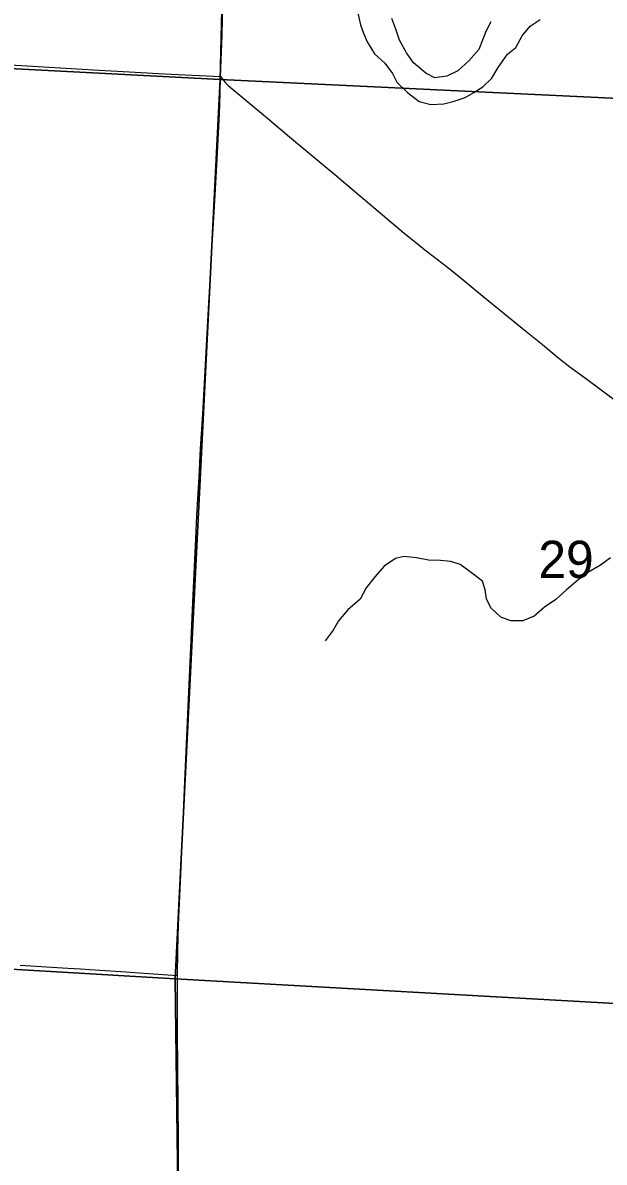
# Model space of a CAD drawing. Extents: x 0 to 34, y 0 to 22.
# Drawn here: x 4.194 to 4.521, y 18.123 to 18.765 of the extents above; entities that cross this region are included whole.
import ezdxf

# ---------------------------------------------------------------- set-up
doc = ezdxf.new("R2010")
doc.units = 0
for name, color, linetype in [('GM_X_Corporation', 7, 'Continuous'), ('GM_X_County_Road', 7, 'Continuous'), ('GM_X_Major_River', 7, 'Continuous'), ('GM_X_Minor_River', 7, 'Continuous'), ('GM_X_Section_Text', 7, 'Continuous'), ('GM_X_State_Route', 7, 'Continuous'), ('GM_X_Township_Road', 7, 'Continuous')]:
    doc.layers.add(name, color=color, linetype=linetype)

msp = doc.modelspace()

# ---------------------------------------------------------------- linework, layer by layer
at = {"layer": 'GM_X_Corporation'}
for points in [[(3.81726, 19.25969), (4.31726, 19.25364), (4.30478, 18.73265), (3.80532, 18.75879)], [(4.31726, 19.25364), (4.81832, 19.23733), (4.81833, 19.23053), (4.81838, 19.17289), (4.81112, 19.17156), (4.80638, 19.17156), (4.80163, 19.172), (4.79778, 19.17363), (4.79126, 19.17541), (4.78267, 19.18), (4.77911, 19.18223), (4.77393, 19.18637), (4.77022, 19.18978), (4.76548, 19.19363), (4.76089, 19.19793), (4.75511, 19.20267), (4.75185, 19.2049), (4.74889, 19.20623), (4.74607, 19.20756), (4.73633, 18.74761), (4.561, 18.7477), (4.54503, 18.72127), (4.30478, 18.73265)], [(4.30478, 18.73265), (4.27934, 18.22655), (3.77934, 18.25611), (3.80532, 18.75879)], [(3.77934, 18.25611), (4.27934, 18.22655), (4.28542, 17.75394), (3.7492, 17.7546)], [(4.27934, 18.22655), (4.66117, 18.20518), (4.66186, 18.19617), (4.66594, 18.18364), (4.67032, 18.16257), (4.67175, 18.15081), (4.67108, 18.13774), (4.67023, 18.12562), (4.66614, 18.11087), (4.66231, 18.10465), (4.65694, 18.09654), (4.65291, 18.09051), (4.65118, 18.08635), (4.64735, 18.08108), (4.73395, 18.08156), (4.72704, 17.74623), (4.28542, 17.75394)]]:
    msp.add_lwpolyline(points, close=True, dxfattribs=at)
msp.add_lwpolyline([(4.66117, 18.20518), (4.27934, 18.22655), (4.30478, 18.73265), (4.54503, 18.72127)], dxfattribs=at)
at = {"layer": 'GM_X_County_Road'}
msp.add_lwpolyline([(4.192, 18.23424), (4.21899, 18.23259), (4.22613, 18.23214), (4.23698, 18.23144), (4.24877, 18.23062), (4.26985, 18.22917), (4.28067, 18.22848)], dxfattribs=at)
at = {"layer": 'GM_X_Major_River'}
for points in [[(4.38239, 18.7699), (4.38387, 18.76344), (4.38554, 18.75868), (4.38759, 18.75374), (4.39172, 18.74707), (4.39756, 18.74191), (4.40187, 18.736), (4.4043, 18.73105), (4.41033, 18.72532), (4.41693, 18.72016), (4.42336, 18.7186), (4.43075, 18.71894), (4.43606, 18.72023), (4.4427, 18.72247), (4.44764, 18.72529), (4.45278, 18.72849), (4.45773, 18.73339), (4.46137, 18.73944), (4.46653, 18.74682), (4.47129, 18.75058), (4.47493, 18.7572), (4.47932, 18.76268), (4.48503, 18.76645)], [(4.45718, 18.76509), (4.45449, 18.7596), (4.45256, 18.75468), (4.45045, 18.74957), (4.44491, 18.74315), (4.43863, 18.73749), (4.43236, 18.73449), (4.42572, 18.73358), (4.42063, 18.73627), (4.41366, 18.742), (4.40971, 18.74772), (4.40578, 18.75477), (4.40374, 18.76104), (4.4015, 18.76694)]]:
    msp.add_lwpolyline(points, dxfattribs=at)
at = {"layer": 'GM_X_Minor_River'}
msp.add_lwpolyline([(4.52457, 18.46348), (4.51905, 18.45934), (4.51183, 18.45521), (4.50631, 18.45088), (4.49983, 18.44541), (4.49393, 18.43994), (4.48746, 18.43562), (4.48156, 18.43072), (4.47529, 18.4281), (4.46847, 18.42795), (4.4628, 18.43007), (4.45715, 18.43541), (4.45472, 18.44036), (4.454, 18.44549), (4.45252, 18.45043), (4.44554, 18.4556), (4.43989, 18.45981), (4.43478, 18.46136), (4.42891, 18.46196), (4.4221, 18.46219), (4.41529, 18.46356), (4.40828, 18.46417), (4.40354, 18.46306), (4.39707, 18.45873), (4.39211, 18.45288), (4.38696, 18.44665), (4.3837, 18.44021), (4.37665, 18.43418), (4.3715, 18.42795), (4.36843, 18.42284), (4.36385, 18.4168)], dxfattribs=at)
at = {"layer": 'GM_X_State_Route'}
msp.add_lwpolyline([(4.28154, 18.09965), (4.28121, 18.13602), (4.28083, 18.17674), (4.28069, 18.19663), (4.28067, 18.22848), (4.28098, 18.24256), (4.28131, 18.2572), (4.28275, 18.28949), (4.28488, 18.33763), (4.28716, 18.38824), (4.28849, 18.41712), (4.28943, 18.43854), (4.29103, 18.47425), (4.29169, 18.48729), (4.29286, 18.50902), (4.29375, 18.52483), (4.2949, 18.54439), (4.29648, 18.57231), (4.29806, 18.60024), (4.30011, 18.63594), (4.30204, 18.67101), (4.30326, 18.69148), (4.30439, 18.7134), (4.30472, 18.7245), (4.30497, 18.7344), (4.30587, 18.75749), (4.30631, 18.77582)], dxfattribs=at)
at = {"layer": 'GM_X_Township_Road'}
for points in [[(3.92462, 18.75398), (3.92513, 18.75396), (3.9372, 18.75351), (3.95081, 18.75299), (3.98465, 18.75147), (4.0039, 18.75057), (4.01879, 18.74992), (4.06367, 18.74774), (4.08273, 18.74681), (4.09793, 18.74593), (4.1274, 18.74415), (4.1485, 18.74302), (4.17642, 18.7414), (4.19597, 18.74029), (4.2332, 18.73812), (4.25678, 18.73675), (4.27322, 18.73577), (4.30497, 18.7344)], [(4.30497, 18.7344), (4.30653, 18.73242), (4.30777, 18.73078), (4.30933, 18.72922), (4.33134, 18.7109), (4.34273, 18.70127), (4.35487, 18.69109), (4.3616, 18.68558), (4.37047, 18.67827), (4.38044, 18.66985), (4.38895, 18.66261), (4.40102, 18.65235), (4.4084, 18.64618), (4.41564, 18.64031), (4.42002, 18.63683), (4.4247, 18.63324), (4.43209, 18.62757), (4.43845, 18.6226), (4.4528, 18.6107), (4.46989, 18.59675), (4.47689, 18.59108), (4.48628, 18.58342), (4.49468, 18.57652), (4.49833, 18.57362), (4.50177, 18.57096), (4.5105, 18.56448), (4.52902, 18.55086)]]:
    msp.add_lwpolyline(points, dxfattribs=at)

# ---------------------------------------------------------------- texts
at = {"layer": 'GM_X_Section_Text'}
msp.add_text('29', height=0.020928, rotation=0.00001, dxfattribs=at).set_placement((4.48402, 18.45216))

doc.saveas('drawing.dxf')
